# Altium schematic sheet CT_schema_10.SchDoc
size 274 x 160 mm
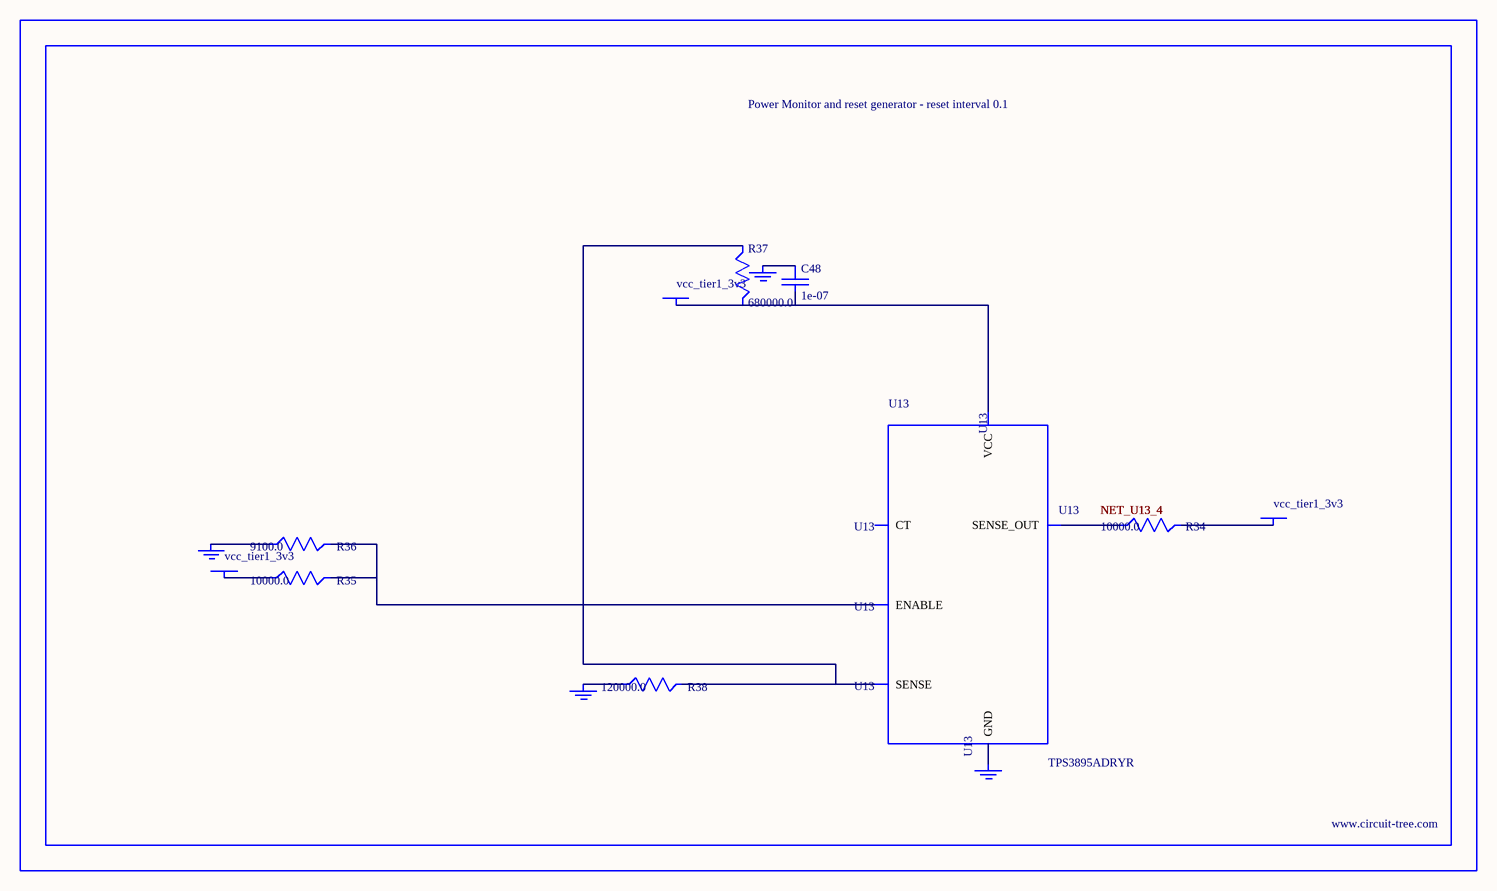
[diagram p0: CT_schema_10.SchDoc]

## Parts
BORDER9  (no value)
C48  1e-07  [C0402]
GND_INSTANCE_9_0  (no value)
GND_INSTANCE_9_1  (no value)
GND_INSTANCE_9_2  (no value)
GND_INSTANCE_9_3  (no value)
POWER_INSTANCE_9_0  vcc_tier1_3v3
POWER_INSTANCE_9_1  vcc_tier1_3v3
POWER_INSTANCE_9_2  vcc_tier1_3v3
R34  10000.0  [R0603]
R35  10000.0  [R0603]
R36  9100.0  [R0603]
R37  680000.0  [R0603]
R38  120000.0  [R0603]
U13  TPS3895ADRYR  [SON-6]

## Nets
NetC48_1: C48.1 GND_INSTANCE_9_2.0(GND)
NetC48_2: C48.2 POWER_INSTANCE_9_2.0(PWR) R37.2 U13.6(VCC)
NetGND_INSTANCE_9_0_0: GND_INSTANCE_9_0.0(GND) R36.1
NetGND_INSTANCE_9_1_0: GND_INSTANCE_9_1.0(GND) R38.1
NetGND_INSTANCE_9_3_0: GND_INSTANCE_9_3.0(GND) U13.2(GND)
NetPOWER_INSTANCE_9_0_0: POWER_INSTANCE_9_0.0(PWR) R35.1
NetPOWER_INSTANCE_9_1_0: POWER_INSTANCE_9_1.0(PWR) R34.2
NetR34_1: R34.1 U13.4(SENSE_OUT)
NetR35_2: R35.2 R36.2 U13.1(ENABLE)
NetR37_1: R37.1 R38.2 U13.3(SENSE)

Not connected (* = marked no-connect by the designer): U13 5(CT)

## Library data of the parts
BORDER9 = BORDER_PAGE9
C48 = C0402C104K3RACTU
GND_INSTANCE_9_0-GND_INSTANCE_9_3 = GND
POWER_INSTANCE_9_0-POWER_INSTANCE_9_2 = PWR
R34 R35 = RC0603JR-0710KL
R36 = RC0603JR-079K1L
R37 = RC0603JR-07680KL
R38 = RC0603JR-07120KL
